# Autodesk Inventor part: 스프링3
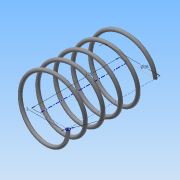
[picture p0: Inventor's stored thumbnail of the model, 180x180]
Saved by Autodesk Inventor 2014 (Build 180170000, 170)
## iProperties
Created: 2015-06
Part Number: 스프링3
Material: 강철, 연강
Document SubType Name: Modeling
Designer: MYHOME
Density: 7.86 g/cm^3
Appearance: 강철
Mass: 1.53479 g
Surface Area: 7.89194 cm^2
Volume: 0.195266 cm^3
Author: MYHOME
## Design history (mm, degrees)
sketch "스케치1"
  geometry: L1 (0, 0)-(8, 0); L2 (8, 0)-(8, 21.5); L3 (8, 21.5)-(0, 21.5); L4 (0, 21.5)-(0, 0); C1 r 0.5 at (8, 0)
  constraints: 8 end point, 2 parallel, 1 centre point, 1 coincident, 1 horizontal, 1 perpendicular
  dimensions: "d0" = 1 diameter of C1; "d1" = 16 diameter of L2 L4; "d2" = 21.5 distance of L3.end L1.start (derived)
feature "코일1" pitch "d3" = 10; turns "d5" = 5; dims "d4" = 21.5 (= d2), "d6" = 0, angle "d7" = 90 deg, angle "d8" = 90 deg, "d9" = 0, "d10" = 0
sketch "스케치2"
  geometry: L1 (-8.5, 0)-(-7.5, 0) reference; 1 further point
  constraints: 1 horizontal alignment
extrude "돌출1" cut sketch "스케치2" distance "d11" = 10; taper "d12" = 0 deg
node "작업 평면1"
sketch "스케치3"
  geometry: L1 (-7.5, 0)-(-8.5, 0) reference; 1 further point
  constraints: 1 horizontal alignment
extrude "돌출2" cut sketch "스케치3" distance "d14" = 10; taper "d15" = 0 deg
node "솔리드1"
node "절단 모서리 투영1"
node "절단 모서리 투영2"
other parameters: "d13" = 21.5 (= d2)
